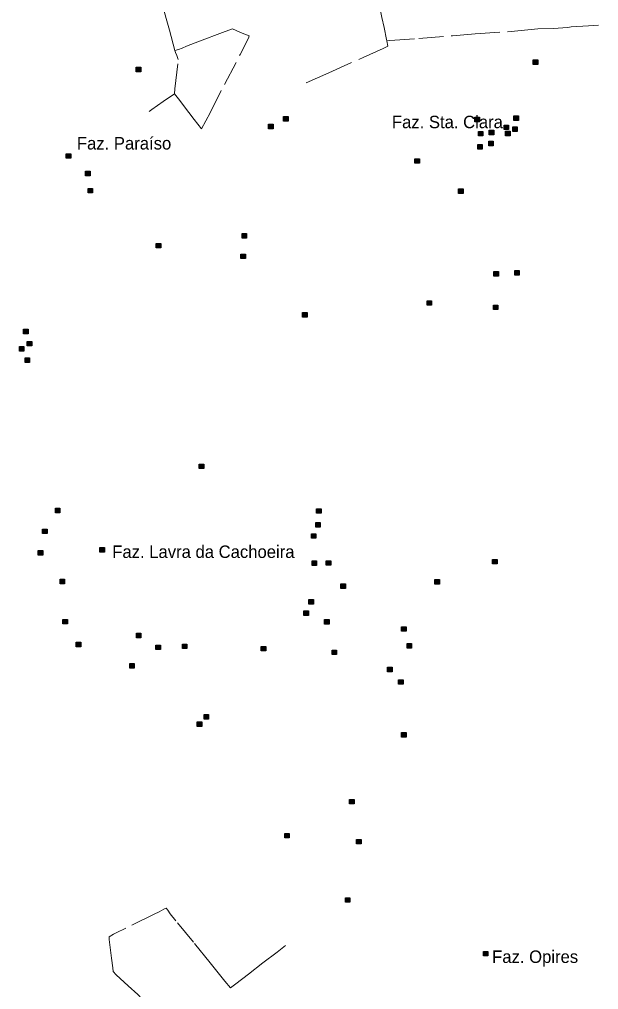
# Model space of a CAD drawing. Extents: x 393.5 to 446.9, y 8064.8 to 8120.4.
# Drawn here: x 393.96 to 401.4, y 8086.21 to 8098.67 of the extents above; entities that cross this region are included whole.
import ezdxf

# ---------------------------------------------------------------- set-up
doc = ezdxf.new("R2010")
doc.units = 0
doc.header["$LTSCALE"] = 0.064
doc.linetypes.add('DOT_DASHED', pattern=[7.7, 5, -1.2, 0.3, -1.2])
doc.layers.add('2', color=7, linetype='Continuous', lineweight=25)
doc.layers.add('22', color=7, linetype='DOT_DASHED', lineweight=13)
doc.layers.add('61', color=7, linetype='Continuous')

msp = doc.modelspace()

# ---------------------------------------------------------------- hatches: boundary and pattern name
at = {"layer": '2'}
for points in [[(400.5631, 8098.151), (400.6211, 8098.151), (400.6211, 8098.093), (400.5631, 8098.093)], [(395.4602, 8098.0559), (395.5182, 8098.0559), (395.5182, 8097.9979), (395.4602, 8097.9979)], [(397.3544, 8097.4212), (397.4124, 8097.4212), (397.4124, 8097.3632), (397.3544, 8097.3632)], [(399.8125, 8097.4125), (399.8705, 8097.4125), (399.8705, 8097.3545), (399.8125, 8097.3545)], [(400.3132, 8097.4302), (400.3712, 8097.4302), (400.3712, 8097.3722), (400.3132, 8097.3722)], [(397.1597, 8097.3228), (397.2177, 8097.3228), (397.2177, 8097.2648), (397.1597, 8097.2648)], [(399.8569, 8097.232), (399.9149, 8097.232), (399.9149, 8097.174), (399.8569, 8097.174)], [(399.9973, 8097.2462), (400.0553, 8097.2462), (400.0553, 8097.1882), (399.9973, 8097.1882)], [(400.1877, 8097.3127), (400.2457, 8097.3127), (400.2457, 8097.2547), (400.1877, 8097.2547)], [(400.2078, 8097.2323), (400.2658, 8097.2323), (400.2658, 8097.1743), (400.2078, 8097.1743)], [(400.2991, 8097.2886), (400.3571, 8097.2886), (400.3571, 8097.2306), (400.2991, 8097.2306)], [(399.9902, 8097.1055), (400.0482, 8097.1055), (400.0482, 8097.0475), (399.9902, 8097.0475)], [(399.8498, 8097.0631), (399.9078, 8097.0631), (399.9078, 8097.0051), (399.8498, 8097.0051)], [(394.5611, 8096.945), (394.6191, 8096.945), (394.6191, 8096.887), (394.5611, 8096.887)], [(399.0427, 8096.8797), (399.1007, 8096.8797), (399.1007, 8096.8217), (399.0427, 8096.8217)], [(394.8076, 8096.7194), (394.8656, 8096.7194), (394.8656, 8096.6614), (394.8076, 8096.6614)], [(394.8407, 8096.4988), (394.8987, 8096.4988), (394.8987, 8096.4408), (394.8407, 8096.4408)], [(399.6036, 8096.4922), (399.6616, 8096.4922), (399.6616, 8096.4342), (399.6036, 8096.4342)], [(396.8203, 8095.9193), (396.8783, 8095.9193), (396.8783, 8095.8613), (396.8203, 8095.8613)], [(395.7179, 8095.7921), (395.7759, 8095.7921), (395.7759, 8095.7341), (395.7179, 8095.7341)], [(396.8057, 8095.655), (396.8637, 8095.655), (396.8637, 8095.597), (396.8057, 8095.597)], [(400.058, 8095.4298), (400.116, 8095.4298), (400.116, 8095.3718), (400.058, 8095.3718)], [(400.3253, 8095.4441), (400.3833, 8095.4441), (400.3833, 8095.3861), (400.3253, 8095.3861)], [(399.199, 8095.0556), (399.257, 8095.0556), (399.257, 8094.9976), (399.199, 8094.9976)], [(400.0497, 8095.0001), (400.1077, 8095.0001), (400.1077, 8094.9421), (400.0497, 8094.9421)], [(397.5974, 8094.9033), (397.6554, 8094.9033), (397.6554, 8094.8453), (397.5974, 8094.8453)], [(394.0111, 8094.6887), (394.0691, 8094.6887), (394.0691, 8094.6307), (394.0111, 8094.6307)], [(393.9578, 8094.4662), (394.0158, 8094.4662), (394.0158, 8094.4082), (393.9578, 8094.4082)], [(394.058, 8094.533), (394.116, 8094.533), (394.116, 8094.475), (394.058, 8094.475)], [(394.0303, 8094.3212), (394.0883, 8094.3212), (394.0883, 8094.2632), (394.0303, 8094.2632)], [(396.2687, 8092.958), (396.3267, 8092.958), (396.3267, 8092.9), (396.2687, 8092.9)], [(394.4208, 8092.39), (394.4788, 8092.39), (394.4788, 8092.332), (394.4208, 8092.332)], [(397.7774, 8092.3829), (397.8354, 8092.3829), (397.8354, 8092.3249), (397.7774, 8092.3249)], [(394.2547, 8092.1224), (394.3127, 8092.1224), (394.3127, 8092.0644), (394.2547, 8092.0644)], [(397.7671, 8092.2055), (397.8251, 8092.2055), (397.8251, 8092.1475), (397.7671, 8092.1475)], [(397.7119, 8092.063), (397.7699, 8092.063), (397.7699, 8092.005), (397.7119, 8092.005)], [(394.1992, 8091.8458), (394.2572, 8091.8458), (394.2572, 8091.7878), (394.1992, 8091.7878)], [(394.9928, 8091.8838), (395.0508, 8091.8838), (395.0508, 8091.8258), (394.9928, 8091.8258)], [(397.9013, 8091.7145), (397.9593, 8091.7145), (397.9593, 8091.6565), (397.9013, 8091.6565)], [(400.041, 8091.7323), (400.099, 8091.7323), (400.099, 8091.6743), (400.041, 8091.6743)], [(397.7207, 8091.7129), (397.7787, 8091.7129), (397.7787, 8091.6549), (397.7207, 8091.6549)], [(394.4799, 8091.4774), (394.5379, 8091.4774), (394.5379, 8091.4194), (394.4799, 8091.4194)], [(399.2983, 8091.4733), (399.3563, 8091.4733), (399.3563, 8091.4153), (399.2983, 8091.4153)], [(398.0906, 8091.4166), (398.1486, 8091.4166), (398.1486, 8091.3586), (398.0906, 8091.3586)], [(397.679, 8091.2171), (397.737, 8091.2171), (397.737, 8091.1591), (397.679, 8091.1591)], [(397.6158, 8091.0696), (397.6738, 8091.0696), (397.6738, 8091.0116), (397.6158, 8091.0116)], [(394.5169, 8090.9608), (394.5749, 8090.9608), (394.5749, 8090.9028), (394.5169, 8090.9028)], [(397.8801, 8090.9597), (397.9381, 8090.9597), (397.9381, 8090.9017), (397.8801, 8090.9017)], [(398.8703, 8090.8679), (398.9283, 8090.8679), (398.9283, 8090.8099), (398.8703, 8090.8099)], [(395.4612, 8090.7845), (395.5192, 8090.7845), (395.5192, 8090.7265), (395.4612, 8090.7265)], [(394.6887, 8090.667), (394.7467, 8090.667), (394.7467, 8090.609), (394.6887, 8090.609)], [(395.7131, 8090.6312), (395.7711, 8090.6312), (395.7711, 8090.5732), (395.7131, 8090.5732)], [(396.0536, 8090.645), (396.1116, 8090.645), (396.1116, 8090.587), (396.0536, 8090.587)], [(397.0667, 8090.6151), (397.1247, 8090.6151), (397.1247, 8090.5571), (397.0667, 8090.5571)], [(398.9414, 8090.6499), (398.9994, 8090.6499), (398.9994, 8090.5919), (398.9414, 8090.5919)], [(397.9764, 8090.5666), (398.0344, 8090.5666), (398.0344, 8090.5086), (397.9764, 8090.5086)], [(395.3765, 8090.393), (395.4345, 8090.393), (395.4345, 8090.335), (395.3765, 8090.335)], [(398.6902, 8090.3479), (398.7482, 8090.3479), (398.7482, 8090.2899), (398.6902, 8090.2899)], [(398.831, 8090.186), (398.889, 8090.186), (398.889, 8090.128), (398.831, 8090.128)], [(396.3311, 8089.7377), (396.3891, 8089.7377), (396.3891, 8089.6797), (396.3311, 8089.6797)], [(396.2435, 8089.644), (396.3015, 8089.644), (396.3015, 8089.586), (396.2435, 8089.586)], [(398.8694, 8089.5081), (398.9274, 8089.5081), (398.9274, 8089.4501), (398.8694, 8089.4501)], [(398.201, 8088.6481), (398.259, 8088.6481), (398.259, 8088.5901), (398.201, 8088.5901)], [(397.3681, 8088.2126), (397.4261, 8088.2126), (397.4261, 8088.1546), (397.3681, 8088.1546)], [(398.2924, 8088.1348), (398.3504, 8088.1348), (398.3504, 8088.0768), (398.2924, 8088.0768)], [(398.1474, 8087.3861), (398.2054, 8087.3861), (398.2054, 8087.3281), (398.1474, 8087.3281)], [(399.9227, 8086.6962), (399.9807, 8086.6962), (399.9807, 8086.6382), (399.9227, 8086.6382)]]:
    msp.add_hatch(color=256, dxfattribs=at).paths.add_polyline_path(points)

# ---------------------------------------------------------------- linework, layer by layer
for points in [[(400.5631, 8098.151), (400.6211, 8098.151), (400.6211, 8098.093), (400.5631, 8098.093)], [(395.4602, 8098.0559), (395.5182, 8098.0559), (395.5182, 8097.9979), (395.4602, 8097.9979)], [(397.3544, 8097.4212), (397.4124, 8097.4212), (397.4124, 8097.3632), (397.3544, 8097.3632)], [(399.8125, 8097.4125), (399.8705, 8097.4125), (399.8705, 8097.3545), (399.8125, 8097.3545)], [(400.3132, 8097.4302), (400.3712, 8097.4302), (400.3712, 8097.3722), (400.3132, 8097.3722)], [(397.1597, 8097.3228), (397.2177, 8097.3228), (397.2177, 8097.2648), (397.1597, 8097.2648)], [(399.8569, 8097.232), (399.9149, 8097.232), (399.9149, 8097.174), (399.8569, 8097.174)], [(399.9973, 8097.2462), (400.0553, 8097.2462), (400.0553, 8097.1882), (399.9973, 8097.1882)], [(400.1877, 8097.3127), (400.2457, 8097.3127), (400.2457, 8097.2547), (400.1877, 8097.2547)], [(400.2078, 8097.2323), (400.2658, 8097.2323), (400.2658, 8097.1743), (400.2078, 8097.1743)], [(400.2991, 8097.2886), (400.3571, 8097.2886), (400.3571, 8097.2306), (400.2991, 8097.2306)], [(399.9902, 8097.1055), (400.0482, 8097.1055), (400.0482, 8097.0475), (399.9902, 8097.0475)], [(399.8498, 8097.0631), (399.9078, 8097.0631), (399.9078, 8097.0051), (399.8498, 8097.0051)], [(394.5611, 8096.945), (394.6191, 8096.945), (394.6191, 8096.887), (394.5611, 8096.887)], [(399.0427, 8096.8797), (399.1007, 8096.8797), (399.1007, 8096.8217), (399.0427, 8096.8217)], [(394.8076, 8096.7194), (394.8656, 8096.7194), (394.8656, 8096.6614), (394.8076, 8096.6614)], [(394.8407, 8096.4988), (394.8987, 8096.4988), (394.8987, 8096.4408), (394.8407, 8096.4408)], [(399.6036, 8096.4922), (399.6616, 8096.4922), (399.6616, 8096.4342), (399.6036, 8096.4342)], [(396.8203, 8095.9193), (396.8783, 8095.9193), (396.8783, 8095.8613), (396.8203, 8095.8613)], [(395.7179, 8095.7921), (395.7759, 8095.7921), (395.7759, 8095.7341), (395.7179, 8095.7341)], [(396.8057, 8095.655), (396.8637, 8095.655), (396.8637, 8095.597), (396.8057, 8095.597)], [(400.058, 8095.4298), (400.116, 8095.4298), (400.116, 8095.3718), (400.058, 8095.3718)], [(400.3253, 8095.4441), (400.3833, 8095.4441), (400.3833, 8095.3861), (400.3253, 8095.3861)], [(399.199, 8095.0556), (399.257, 8095.0556), (399.257, 8094.9976), (399.199, 8094.9976)], [(400.0497, 8095.0001), (400.1077, 8095.0001), (400.1077, 8094.9421), (400.0497, 8094.9421)], [(397.5974, 8094.9033), (397.6554, 8094.9033), (397.6554, 8094.8453), (397.5974, 8094.8453)], [(394.0111, 8094.6887), (394.0691, 8094.6887), (394.0691, 8094.6307), (394.0111, 8094.6307)], [(393.9578, 8094.4662), (394.0158, 8094.4662), (394.0158, 8094.4082), (393.9578, 8094.4082)], [(394.058, 8094.533), (394.116, 8094.533), (394.116, 8094.475), (394.058, 8094.475)], [(394.0303, 8094.3212), (394.0883, 8094.3212), (394.0883, 8094.2632), (394.0303, 8094.2632)], [(396.2687, 8092.958), (396.3267, 8092.958), (396.3267, 8092.9), (396.2687, 8092.9)], [(394.4208, 8092.39), (394.4788, 8092.39), (394.4788, 8092.332), (394.4208, 8092.332)], [(397.7774, 8092.3829), (397.8354, 8092.3829), (397.8354, 8092.3249), (397.7774, 8092.3249)], [(394.2547, 8092.1224), (394.3127, 8092.1224), (394.3127, 8092.0644), (394.2547, 8092.0644)], [(397.7671, 8092.2055), (397.8251, 8092.2055), (397.8251, 8092.1475), (397.7671, 8092.1475)], [(397.7119, 8092.063), (397.7699, 8092.063), (397.7699, 8092.005), (397.7119, 8092.005)], [(394.1992, 8091.8458), (394.2572, 8091.8458), (394.2572, 8091.7878), (394.1992, 8091.7878)], [(394.9928, 8091.8838), (395.0508, 8091.8838), (395.0508, 8091.8258), (394.9928, 8091.8258)], [(397.9013, 8091.7145), (397.9593, 8091.7145), (397.9593, 8091.6565), (397.9013, 8091.6565)], [(400.041, 8091.7323), (400.099, 8091.7323), (400.099, 8091.6743), (400.041, 8091.6743)], [(397.7207, 8091.7129), (397.7787, 8091.7129), (397.7787, 8091.6549), (397.7207, 8091.6549)], [(394.4799, 8091.4774), (394.5379, 8091.4774), (394.5379, 8091.4194), (394.4799, 8091.4194)], [(399.2983, 8091.4733), (399.3563, 8091.4733), (399.3563, 8091.4153), (399.2983, 8091.4153)], [(398.0906, 8091.4166), (398.1486, 8091.4166), (398.1486, 8091.3586), (398.0906, 8091.3586)], [(397.679, 8091.2171), (397.737, 8091.2171), (397.737, 8091.1591), (397.679, 8091.1591)], [(397.6158, 8091.0696), (397.6738, 8091.0696), (397.6738, 8091.0116), (397.6158, 8091.0116)], [(394.5169, 8090.9608), (394.5749, 8090.9608), (394.5749, 8090.9028), (394.5169, 8090.9028)], [(397.8801, 8090.9597), (397.9381, 8090.9597), (397.9381, 8090.9017), (397.8801, 8090.9017)], [(398.8703, 8090.8679), (398.9283, 8090.8679), (398.9283, 8090.8099), (398.8703, 8090.8099)], [(395.4612, 8090.7845), (395.5192, 8090.7845), (395.5192, 8090.7265), (395.4612, 8090.7265)], [(394.6887, 8090.667), (394.7467, 8090.667), (394.7467, 8090.609), (394.6887, 8090.609)], [(395.7131, 8090.6312), (395.7711, 8090.6312), (395.7711, 8090.5732), (395.7131, 8090.5732)], [(396.0536, 8090.645), (396.1116, 8090.645), (396.1116, 8090.587), (396.0536, 8090.587)], [(397.0667, 8090.6151), (397.1247, 8090.6151), (397.1247, 8090.5571), (397.0667, 8090.5571)], [(398.9414, 8090.6499), (398.9994, 8090.6499), (398.9994, 8090.5919), (398.9414, 8090.5919)], [(397.9764, 8090.5666), (398.0344, 8090.5666), (398.0344, 8090.5086), (397.9764, 8090.5086)], [(395.3765, 8090.393), (395.4345, 8090.393), (395.4345, 8090.335), (395.3765, 8090.335)], [(398.6902, 8090.3479), (398.7482, 8090.3479), (398.7482, 8090.2899), (398.6902, 8090.2899)], [(398.831, 8090.186), (398.889, 8090.186), (398.889, 8090.128), (398.831, 8090.128)], [(396.3311, 8089.7377), (396.3891, 8089.7377), (396.3891, 8089.6797), (396.3311, 8089.6797)], [(396.2435, 8089.644), (396.3015, 8089.644), (396.3015, 8089.586), (396.2435, 8089.586)], [(398.8694, 8089.5081), (398.9274, 8089.5081), (398.9274, 8089.4501), (398.8694, 8089.4501)], [(398.201, 8088.6481), (398.259, 8088.6481), (398.259, 8088.5901), (398.201, 8088.5901)], [(397.3681, 8088.2126), (397.4261, 8088.2126), (397.4261, 8088.1546), (397.3681, 8088.1546)], [(398.2924, 8088.1348), (398.3504, 8088.1348), (398.3504, 8088.0768), (398.2924, 8088.0768)], [(398.1474, 8087.3861), (398.2054, 8087.3861), (398.2054, 8087.3281), (398.1474, 8087.3281)], [(399.9227, 8086.6962), (399.9807, 8086.6962), (399.9807, 8086.6382), (399.9227, 8086.6382)]]:
    msp.add_lwpolyline(points, close=True, dxfattribs=at)
at = {"layer": '22'}
for p, q in [((395.9523, 8097.714), (395.951, 8097.7131)), ((395.9524, 8097.714), (395.9525, 8097.7155))]:
    msp.add_line(p, q, dxfattribs=at)
for points in [[(398.6812, 8098.3934), (398.6761, 8098.4112), (398.6473, 8098.5648), (398.6161, 8098.6962), (398.5816, 8098.8661), (398.5547, 8098.9964), (398.5233, 8099.1623), (398.4902, 8099.3367), (398.4723, 8099.4223), (398.4405, 8099.5569), (398.4226, 8099.6233), (398.4136, 8099.6731), (398.4136, 8099.7127), (398.4175, 8099.7293), (398.4737, 8099.7421), (398.6028, 8099.7778), (398.7153, 8099.8098), (398.9486, 8099.8724), (399.1046, 8099.9184)], [(395.9576, 8098.2726), (395.8857, 8098.5332), (395.8434, 8098.6804), (395.8192, 8098.7751), (395.7577, 8098.9847), (395.7355, 8099.0734)], [(398.6812, 8098.3933), (398.7183, 8098.3971), (399.0908, 8098.425), (399.5259, 8098.4611), (399.8147, 8098.4837), (400.2801, 8098.5153), (400.4089, 8098.5296), (400.6221, 8098.5471), (400.8193, 8098.555), (401.0062, 8098.5645), (401.0501, 8098.5728)], [(401.0501, 8098.5728), (401.2719, 8098.5887), (401.4028, 8098.5983)], [(395.9524, 8097.714), (396.0038, 8097.6492), (396.1369, 8097.4759), (396.2034, 8097.3852), (396.2982, 8097.2663), (396.41, 8097.4696), (396.5926, 8097.8347), (396.7966, 8098.2211), (396.9041, 8098.4297), (396.9102, 8098.46), (396.8013, 8098.5003), (396.6964, 8098.5486), (396.5673, 8098.5003), (396.2728, 8098.3894), (396.1054, 8098.3249), (396.0489, 8098.3007), (396.0037, 8098.2857), (395.9576, 8098.2726)], [(397.6419, 8097.8535), (397.9358, 8097.9842), (398.3784, 8098.1826), (398.6339, 8098.2975), (398.6953, 8098.3243), (398.6813, 8098.3931), (398.6812, 8098.3933), (398.6812, 8098.3934)], [(395.9525, 8097.7155), (395.9566, 8097.7799), (395.9996, 8098.1559), (395.9794, 8098.2063), (395.9633, 8098.2446), (395.9576, 8098.2726)], [(395.951, 8097.7131), (395.8038, 8097.6171), (395.6621, 8097.5147), (395.6246, 8097.488)], [(395.8155, 8087.2375), (395.7536, 8087.2062), (395.69, 8087.1744), (395.3257, 8086.994), (395.2029, 8086.9355)], [(397.3789, 8086.7721), (397.2704, 8086.688), (397.0871, 8086.5478), (396.9019, 8086.4057), (396.741, 8086.2805), (396.6699, 8086.23), (396.5991, 8086.312), (396.4099, 8086.5486), (396.1939, 8086.8142), (395.9703, 8087.0877), (395.8974, 8087.1778), (395.8637, 8087.2264), (395.8453, 8087.2519), (395.8155, 8087.2375)], [(395.2029, 8086.9355), (395.1663, 8086.9172), (395.1102, 8086.8835), (395.1102, 8086.8499), (395.1437, 8086.6096), (395.1568, 8086.4844), (395.1624, 8086.4377), (395.2017, 8086.3965), (395.357, 8086.2545), (395.4804, 8086.1442), (395.5347, 8086.0844)]]:
    msp.add_lwpolyline(points, dxfattribs=at)

# ---------------------------------------------------------------- texts
at = {"layer": '61'}
for s, p in [('Faz. Sta. Clara', (398.7459, 8097.2725)), ('Faz. Paraíso', (394.6968, 8096.9986)), ('Faz. Lavra da Cachoeira', (395.1512, 8091.7511)), ('Faz. Opires', (400.0342, 8086.5478))]:
    msp.add_text(s, height=0.16, dxfattribs=at).set_placement(p)

doc.saveas('drawing.dxf')
